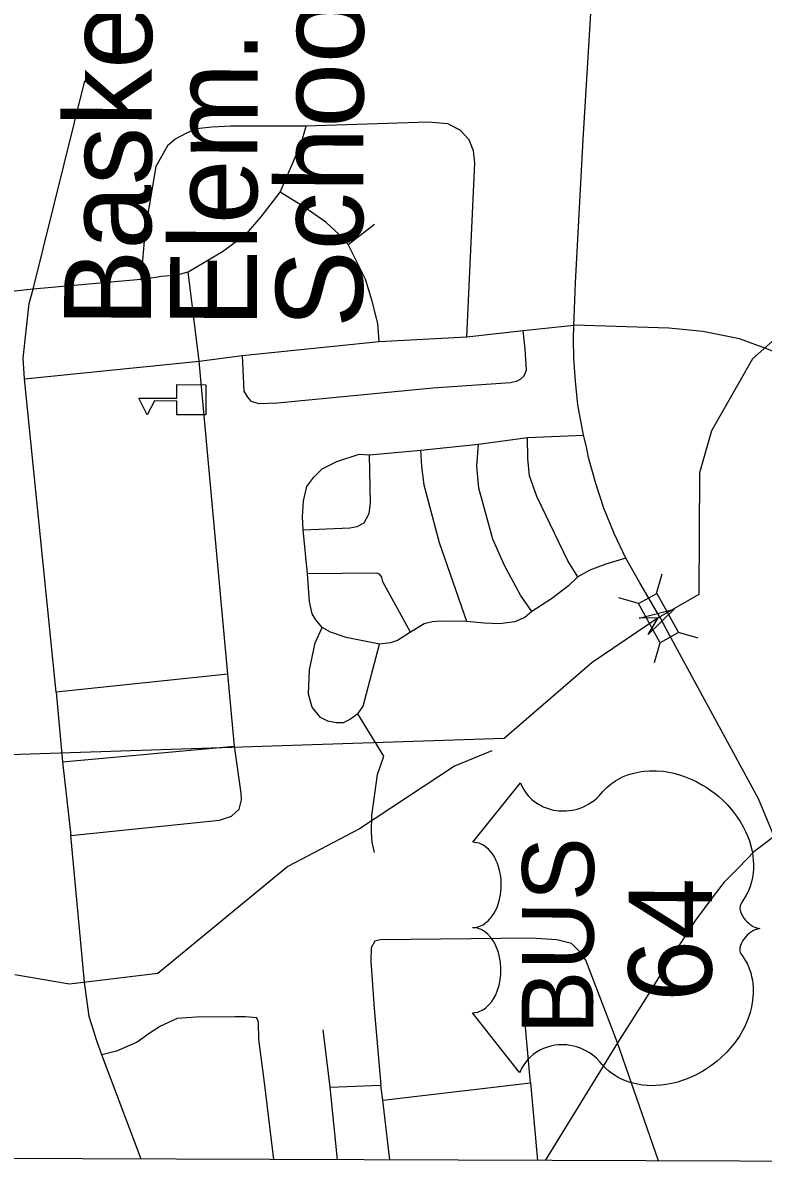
# Model space of a CAD drawing. Extents: x 2364794 to 2387902, y 795230 to 810426.
# Drawn here: x 2366376.7 to 2366649.7, y 800399.4 to 800821.1 of the extents above; entities that cross this region are included whole.
import ezdxf

# ---------------------------------------------------------------- set-up
doc = ezdxf.new("R2010")
doc.units = 0
for name, color, linetype in [('Default', 7, 'Continuous'), ('Plot Label CELL', 7, 'Continuous'), ('Plot Shape CELL', 7, 'Continuous')]:
    doc.layers.add(name, color=color, linetype=linetype)

msp = doc.modelspace()

# ---------------------------------------------------------------- linework, layer by layer
at = {"layer": 'Default'}
for p, q in [((2366610.39, 800610.6), (2366612.48, 800617.85)), ((2366603.79, 800606.95), (2366596.54, 800609.03)), ((2366625.77, 800594.12), (2366618.52, 800596.21)), ((2366609.68, 800585.22), (2366611.76, 800592.47)), ((2366599.77, 800543.72), (2366601.6, 800544.28)), ((2366601.6, 800544.28), (2366602.56, 800544.54)), ((2366602.56, 800544.54), (2366604.72, 800544.94)), ((2366604.72, 800544.94), (2366605.79, 800545.09)), ((2366605.79, 800545.09), (2366607.89, 800545.25)), ((2366607.89, 800545.25), (2366610.43, 800545.25)), ((2366610.43, 800545.25), (2366612.85, 800545.05)), ((2366612.85, 800545.05), (2366615.66, 800544.58)), ((2366615.66, 800544.58), (2366617.35, 800544.2)), ((2366617.35, 800544.2), (2366619.31, 800543.62)), ((2366542.68, 800518.86), (2366560.26, 800540.77)), ((2366560.26, 800540.77), (2366560.46, 800540.25)), ((2366560.46, 800540.25), (2366561.04, 800539.05)), ((2366592.05, 800539.03), (2366593.66, 800540.4)), ((2366593.66, 800540.4), (2366594.41, 800540.95)), ((2366594.41, 800540.95), (2366595.26, 800541.52)), ((2366595.26, 800541.52), (2366596.13, 800542.03)), ((2366596.13, 800542.03), (2366597.06, 800542.55)), ((2366597.06, 800542.55), (2366597.88, 800542.96)), ((2366597.88, 800542.96), (2366599.77, 800543.72)), ((2366619.31, 800543.62), (2366621.01, 800543.05)), ((2366621.01, 800543.05), (2366623.51, 800542.04)), ((2366623.51, 800542.04), (2366625.32, 800541.14)), ((2366625.32, 800541.14), (2366627.45, 800539.98)), ((2366627.45, 800539.98), (2366628.73, 800539.18)), ((2366561.04, 800539.05), (2366561.59, 800538.11)), ((2366561.59, 800538.11), (2366562.65, 800536.59)), ((2366562.65, 800536.59), (2366563.23, 800535.94)), ((2366563.23, 800535.94), (2366563.84, 800535.29)), ((2366588.47, 800535.2), (2366589.41, 800536.11)), ((2366589.41, 800536.11), (2366590.56, 800537.46)), ((2366590.56, 800537.46), (2366591.21, 800538.19)), ((2366591.21, 800538.19), (2366592.05, 800539.03)), ((2366628.73, 800539.18), (2366630.1, 800538.26)), ((2366630.1, 800538.26), (2366631.68, 800537.1)), ((2366631.68, 800537.1), (2366633.37, 800535.74)), ((2366633.37, 800535.74), (2366635.14, 800534.11)), ((2366563.84, 800535.29), (2366564.49, 800534.69)), ((2366564.49, 800534.69), (2366565.1, 800534.16)), ((2366565.1, 800534.16), (2366565.98, 800533.52)), ((2366565.98, 800533.52), (2366566.86, 800532.95)), ((2366566.86, 800532.95), (2366567.83, 800532.39)), ((2366567.83, 800532.39), (2366568.67, 800531.97)), ((2366568.67, 800531.97), (2366570.44, 800531.29)), ((2366570.44, 800531.29), (2366571.55, 800530.97)), ((2366581.11, 800531.14), (2366582.33, 800531.52)), ((2366582.33, 800531.52), (2366583.51, 800532)), ((2366583.51, 800532), (2366585.42, 800533)), ((2366585.42, 800533), (2366587.38, 800534.28)), ((2366587.38, 800534.28), (2366588.47, 800535.2)), ((2366635.14, 800534.11), (2366636.45, 800532.8)), ((2366636.45, 800532.8), (2366637.97, 800531.08)), ((2366571.55, 800530.97), (2366572.5, 800530.75)), ((2366572.5, 800530.75), (2366574.46, 800530.49)), ((2366574.46, 800530.49), (2366575.39, 800530.42)), ((2366575.39, 800530.42), (2366576.31, 800530.42)), ((2366576.31, 800530.42), (2366577.29, 800530.46)), ((2366577.29, 800530.46), (2366578.22, 800530.55)), ((2366578.22, 800530.55), (2366579.2, 800530.72)), ((2366579.2, 800530.72), (2366580.05, 800530.87)), ((2366580.05, 800530.87), (2366581.11, 800531.14)), ((2366637.97, 800531.08), (2366638.83, 800530.04)), ((2366638.83, 800530.04), (2366639.94, 800528.56)), ((2366639.94, 800528.56), (2366641.28, 800526.53)), ((2366641.28, 800526.53), (2366642.43, 800524.53)), ((2366642.43, 800524.53), (2366643.29, 800522.82)), ((2366643.29, 800522.82), (2366643.94, 800521.31)), ((2366543.33, 800518.84), (2366542.68, 800518.86)), ((2366544.1, 800518.73), (2366543.33, 800518.84)), ((2366544.98, 800518.51), (2366544.1, 800518.73)), ((2366643.94, 800521.31), (2366644.67, 800519.37)), ((2366644.67, 800519.37), (2366645.55, 800516.12)), ((2366545.81, 800518.16), (2366544.98, 800518.51)), ((2366546.6, 800517.78), (2366545.81, 800518.16)), ((2366547.37, 800517.24), (2366546.6, 800517.78)), ((2366548.42, 800516.33), (2366547.37, 800517.24)), ((2366549.29, 800515.37), (2366548.42, 800516.33)), ((2366549.94, 800514.56), (2366549.29, 800515.37)), ((2366550.63, 800513.46), (2366549.94, 800514.56)), ((2366645.55, 800516.12), (2366645.8, 800514.94)), ((2366645.8, 800514.94), (2366646, 800513.54)), ((2366551.33, 800512.09), (2366550.63, 800513.46)), ((2366551.79, 800511.04), (2366551.33, 800512.09)), ((2366552.21, 800509.84), (2366551.79, 800511.04)), ((2366646, 800513.54), (2366646.13, 800512.22)), ((2366646.13, 800512.22), (2366646.2, 800510.95)), ((2366646.2, 800510.95), (2366646.19, 800509.24)), ((2366552.56, 800508.52), (2366552.21, 800509.84)), ((2366552.77, 800507.52), (2366552.56, 800508.52)), ((2366552.98, 800506.27), (2366552.77, 800507.52)), ((2366553.1, 800505.14), (2366552.98, 800506.27)), ((2366646.06, 800507.54), (2366645.82, 800505.93)), ((2366646.19, 800509.24), (2366646.06, 800507.54)), ((2366553.05, 800500.68), (2366553.14, 800501.87)), ((2366553.16, 800504.04), (2366553.1, 800505.14)), ((2366553.14, 800501.87), (2366553.17, 800502.85)), ((2366553.17, 800502.85), (2366553.16, 800504.04)), ((2366644.94, 800502.51), (2366644.31, 800500.92)), ((2366645.46, 800504.26), (2366644.94, 800502.51)), ((2366645.82, 800505.93), (2366645.46, 800504.26)), ((2366552.4, 800497.22), (2366552.67, 800498.37)), ((2366552.67, 800498.37), (2366552.87, 800499.51)), ((2366552.87, 800499.51), (2366553.05, 800500.68)), ((2366643.51, 800499.31), (2366641.79, 800496.6)), ((2366644.31, 800500.92), (2366643.51, 800499.31)), ((2366550.47, 800492.62), (2366551.36, 800494.37)), ((2366551.36, 800494.37), (2366551.74, 800495.22)), ((2366551.74, 800495.22), (2366552.06, 800496.1)), ((2366552.06, 800496.1), (2366552.4, 800497.22)), ((2366641.25, 800495.38), (2366641.19, 800494.33)), ((2366641.19, 800494.33), (2366641.4, 800493.34)), ((2366641.37, 800495.82), (2366641.25, 800495.38)), ((2366641.79, 800496.6), (2366641.37, 800495.82)), ((2366641.4, 800493.34), (2366641.8, 800492.33)), ((2366547.25, 800488.99), (2366548.41, 800489.97)), ((2366548.41, 800489.97), (2366548.99, 800490.58)), ((2366548.99, 800490.58), (2366549.44, 800491.13)), ((2366549.44, 800491.13), (2366550.47, 800492.62)), ((2366641.8, 800492.33), (2366642.12, 800491.72)), ((2366642.12, 800491.72), (2366642.65, 800490.9)), ((2366642.65, 800490.9), (2366643.14, 800490.28)), ((2366643.14, 800490.28), (2366643.85, 800489.52)), ((2366643.85, 800489.52), (2366644.45, 800489)), ((2366542.59, 800487.42), (2366543.61, 800487.49)), ((2366543.81, 800487.32), (2366542.59, 800487.42)), ((2366543.61, 800487.49), (2366544.25, 800487.59)), ((2366544.39, 800487.19), (2366543.81, 800487.32)), ((2366544.25, 800487.59), (2366544.87, 800487.76)), ((2366545.71, 800486.72), (2366544.39, 800487.19)), ((2366544.87, 800487.76), (2366545.54, 800488.01)), ((2366545.54, 800488.01), (2366546.47, 800488.48)), ((2366546.34, 800486.38), (2366545.71, 800486.72)), ((2366546.98, 800485.99), (2366546.34, 800486.38)), ((2366546.47, 800488.48), (2366547.25, 800488.99)), ((2366548.14, 800485.06), (2366546.98, 800485.99)), ((2366549.25, 800483.89), (2366548.14, 800485.06)), ((2366644.76, 800485.33), (2366643.87, 800484.57)), ((2366644.45, 800489), (2366644.91, 800488.6)), ((2366645.45, 800485.81), (2366644.76, 800485.33)), ((2366644.91, 800488.6), (2366646.12, 800487.83)), ((2366646.23, 800486.28), (2366645.45, 800485.81)), ((2366646.12, 800487.83), (2366646.69, 800487.56)), ((2366647.14, 800486.68), (2366646.23, 800486.28)), ((2366646.69, 800487.56), (2366647.43, 800487.27)), ((2366648.51, 800487.02), (2366647.14, 800486.68)), ((2366647.43, 800487.27), (2366648.51, 800487.02)), ((2366549.84, 800483.06), (2366549.25, 800483.89)), ((2366550.51, 800482.01), (2366549.84, 800483.06)), ((2366551.21, 800480.69), (2366550.51, 800482.01)), ((2366551.7, 800479.5), (2366551.21, 800480.69)), ((2366641.38, 800480.82), (2366641.18, 800480.03)), ((2366641.63, 800481.47), (2366641.38, 800480.82)), ((2366641.99, 800482.17), (2366641.63, 800481.47)), ((2366642.53, 800483.05), (2366641.99, 800482.17)), ((2366643.21, 800483.88), (2366642.53, 800483.05)), ((2366643.87, 800484.57), (2366643.21, 800483.88)), ((2366552.14, 800478.21), (2366551.7, 800479.5)), ((2366552.43, 800477.06), (2366552.14, 800478.21)), ((2366552.9, 800474.56), (2366552.43, 800477.06)), ((2366641.18, 800480.03), (2366641.13, 800479.38)), ((2366641.13, 800479.38), (2366641.14, 800478.85)), ((2366641.14, 800478.85), (2366641.3, 800478.11)), ((2366641.3, 800478.11), (2366642.02, 800477.12)), ((2366642.02, 800477.12), (2366642.66, 800476.17)), ((2366553.06, 800472.31), (2366552.9, 800474.56)), ((2366553.02, 800470.22), (2366553.06, 800472.31)), ((2366642.66, 800476.17), (2366643.29, 800475.15)), ((2366643.29, 800475.15), (2366643.94, 800473.92)), ((2366643.94, 800473.92), (2366644.35, 800473.03)), ((2366644.35, 800473.03), (2366644.76, 800471.96)), ((2366552.38, 800466.17), (2366552.78, 800468.1)), ((2366552.78, 800468.1), (2366553.02, 800470.22)), ((2366644.76, 800471.96), (2366645.17, 800470.72)), ((2366645.17, 800470.72), (2366645.52, 800469.36)), ((2366645.52, 800469.36), (2366645.79, 800467.98)), ((2366551.11, 800462.58), (2366551.83, 800464.28)), ((2366551.83, 800464.28), (2366552.38, 800466.17)), ((2366645.79, 800467.98), (2366645.98, 800466.75)), ((2366645.98, 800466.75), (2366646.09, 800465.44)), ((2366646.09, 800465.44), (2366646.12, 800464.26)), ((2366646.12, 800464.26), (2366646.11, 800463.03)), ((2366548.64, 800458.9), (2366549.72, 800460.2)), ((2366549.72, 800460.2), (2366550.3, 800461.08)), ((2366550.3, 800461.08), (2366551.11, 800462.58)), ((2366645.89, 800460.54), (2366645.64, 800458.88)), ((2366646.01, 800461.88), (2366645.89, 800460.54)), ((2366646.11, 800463.03), (2366646.01, 800461.88)), ((2366542.53, 800455.97), (2366543.44, 800456.03)), ((2366559.95, 800433.94), (2366542.53, 800455.97)), ((2366543.44, 800456.03), (2366544.52, 800456.24)), ((2366544.52, 800456.24), (2366545.07, 800456.41)), ((2366545.07, 800456.41), (2366546.14, 800456.91)), ((2366546.14, 800456.91), (2366547.4, 800457.74)), ((2366547.4, 800457.74), (2366548.64, 800458.9)), ((2366644.93, 800456.05), (2366644.45, 800454.56)), ((2366645.32, 800457.51), (2366644.93, 800456.05)), ((2366645.64, 800458.88), (2366645.32, 800457.51)), ((2366643.84, 800452.97), (2366642.96, 800450.97)), ((2366644.45, 800454.56), (2366643.84, 800452.97)), ((2366640.98, 800447.4), (2366639.19, 800444.84)), ((2366642.24, 800449.59), (2366640.98, 800447.4)), ((2366642.96, 800450.97), (2366642.24, 800449.59)), ((2366568.73, 800442.82), (2366567.67, 800442.33)), ((2366570.19, 800443.36), (2366568.73, 800442.82)), ((2366571.46, 800443.7), (2366570.19, 800443.36)), ((2366572.92, 800443.98), (2366571.46, 800443.7)), ((2366574.44, 800444.14), (2366572.92, 800443.98)), ((2366575.74, 800444.18), (2366574.44, 800444.14)), ((2366577.31, 800444.11), (2366575.74, 800444.18)), ((2366578.57, 800443.94), (2366577.31, 800444.11)), ((2366579.9, 800443.67), (2366578.57, 800443.94)), ((2366580.94, 800443.41), (2366579.9, 800443.67)), ((2366582.42, 800442.9), (2366580.94, 800443.41)), ((2366583.38, 800442.5), (2366582.42, 800442.9)), ((2366637.61, 800442.9), (2366636.32, 800441.49)), ((2366639.19, 800444.84), (2366637.61, 800442.9)), ((2366562.81, 800438.62), (2366562.08, 800437.69)), ((2366563.79, 800439.59), (2366562.81, 800438.62)), ((2366564.88, 800440.56), (2366563.79, 800439.59)), ((2366566.22, 800441.49), (2366564.88, 800440.56)), ((2366567.67, 800442.33), (2366566.22, 800441.49)), ((2366584.66, 800441.82), (2366583.38, 800442.5)), ((2366585.53, 800441.32), (2366584.66, 800441.82)), ((2366586.5, 800440.68), (2366585.53, 800441.32)), ((2366587.55, 800439.87), (2366586.5, 800440.68)), ((2366588.3, 800439.21), (2366587.55, 800439.87)), ((2366589.54, 800437.93), (2366588.3, 800439.21)), ((2366634.18, 800439.4), (2366632.79, 800438.18)), ((2366636.32, 800441.49), (2366634.18, 800439.4)), ((2366560.23, 800434.62), (2366559.95, 800433.94)), ((2366560.76, 800435.69), (2366560.23, 800434.62)), ((2366561.44, 800436.81), (2366560.76, 800435.69)), ((2366562.08, 800437.69), (2366561.44, 800436.81)), ((2366590.41, 800436.86), (2366589.54, 800437.93)), ((2366591.52, 800435.69), (2366590.41, 800436.86)), ((2366592.74, 800434.56), (2366591.52, 800435.69)), ((2366593.84, 800433.7), (2366592.74, 800434.56)), ((2366628.48, 800435.04), (2366627.15, 800434.24)), ((2366630.29, 800436.26), (2366628.48, 800435.04)), ((2366632.79, 800438.18), (2366630.29, 800436.26)), ((2366595.13, 800432.83), (2366593.84, 800433.7)), ((2366596.34, 800432.13), (2366595.13, 800432.83)), ((2366597.79, 800431.4), (2366596.34, 800432.13)), ((2366599.31, 800430.77), (2366597.79, 800431.4)), ((2366600.68, 800430.3), (2366599.31, 800430.77)), ((2366601.81, 800429.98), (2366600.68, 800430.3)), ((2366617.18, 800430.15), (2366615.3, 800429.74)), ((2366618.26, 800430.44), (2366617.18, 800430.15)), ((2366619.95, 800430.97), (2366618.26, 800430.44)), ((2366621.73, 800431.62), (2366619.95, 800430.97)), ((2366623.68, 800432.45), (2366621.73, 800431.62)), ((2366625.02, 800433.08), (2366623.68, 800432.45)), ((2366627.15, 800434.24), (2366625.02, 800433.08)), ((2366603.38, 800429.63), (2366601.81, 800429.98)), ((2366605.21, 800429.33), (2366603.38, 800429.63)), ((2366606.93, 800429.15), (2366605.21, 800429.33)), ((2366608.41, 800429.1), (2366606.93, 800429.15)), ((2366610.19, 800429.12), (2366608.41, 800429.1)), ((2366612.13, 800429.25), (2366610.19, 800429.12)), ((2366613.96, 800429.49), (2366612.13, 800429.25)), ((2366615.3, 800429.74), (2366613.96, 800429.49))]:
    msp.add_line(p, q, dxfattribs=at)
for points in [[(2365221.07, 800406.27), (2365228.68, 802558.07), (2367168.28, 802551.22), (2367160.68, 800399.42)], [(2365221.07, 800406.27), (2365228.68, 802558.07), (2367168.28, 802551.22), (2367160.68, 800399.42)], [(2366444.21, 800676.55), (2366433.5, 800676.59), (2366433.52, 800681.63), (2366425.31, 800681.66), (2366422.64, 800676.52), (2366419.47, 800682.73), (2366433.53, 800682.68), (2366433.54, 800687.71), (2366444.25, 800687.67)], [(2366611.76, 800592.47), (2366603.76, 800606.93), (2366610.52, 800610.67), (2366618.52, 800596.21)], [(2366603.98, 800601.58), (2366616.9, 800604.87), (2366607.36, 800595.56), (2366611.08, 800601.61)]]:
    msp.add_lwpolyline(points, close=True, dxfattribs=at)
at = {"layer": 'Plot Label CELL'}
for p, q in [((2366380.52, 800722.89), (2366399.54, 800799.77)), ((2366496.67, 800739.39), (2366506.45, 800746.9)), ((2366420.26, 800726.49), (2366380.52, 800722.89)), ((2366441.73, 800696.3), (2366437.74, 800729.27)), ((2366561.2, 800707.66), (2366579.9, 800709.63)), ((2366508.14, 800703.63), (2366540.47, 800705.3)), ((2366540.47, 800705.3), (2366561.2, 800707.66)), ((2366457.66, 800698.4), (2366508.14, 800703.63)), ((2366377.3, 800689.85), (2366441.73, 800696.3)), ((2366441.73, 800696.3), (2366457.66, 800698.4)), ((2366452.33, 800580.94), (2366441.73, 800696.3)), ((2366389.02, 800574.28), (2366377.3, 800689.85)), ((2366544.74, 800665.68), (2366562.87, 800668.24)), ((2366562.87, 800668.24), (2366583.52, 800669.1)), ((2366504.56, 800661.84), (2366523.57, 800663.53)), ((2366523.57, 800663.53), (2366544.74, 800665.68)), ((2366481.75, 800617.94), (2366480.08, 800634.09)), ((2366452.33, 800580.94), (2366389.02, 800574.28)), ((2366454.75, 800554.31), (2366452.33, 800580.94)), ((2366389.02, 800574.28), (2366391.39, 800548.53)), ((2366391.39, 800548.53), (2366454.75, 800554.31)), ((2366391.39, 800548.53), (2366394.38, 800521.33)), ((2366564.01, 800430.18), (2366561.85, 800453.34)), ((2366490.02, 800428.53), (2366487.45, 800449.66)), ((2366611.19, 800401.36), (2366596.04, 800444.87)), ((2366509.51, 800423.79), (2366564.01, 800430.18)), ((2366564.01, 800430.18), (2366566.56, 800401.52)), ((2366490.02, 800428.53), (2366508.72, 800429.28)), ((2366492.83, 800401.78), (2366490.02, 800428.53)), ((2366509.51, 800423.79), (2366508.72, 800429.28)), ((2366512.04, 800401.71), (2366509.51, 800423.79))]:
    msp.add_line(p, q, dxfattribs=at)
for points in [[(2366788.16, 801000.92), (2366786.07, 800825.96), (2366768.32, 800782.08), (2366754.11, 800740.13), (2366744.07, 800730.01), (2366706.87, 800726.96), (2366678.73, 800721.27), (2366665.69, 800714.75), (2366645.89, 800697.21), (2366630.73, 800670.7), (2366626.28, 800655.17), (2366626.04, 800610.32), (2366611.08, 800601.61), (2366586.72, 800585.24), (2366554.22, 800557.13), (2366241.62, 800546.88), (2366175.9, 800494.71), (2366184.14, 800414.1)], [(2366540.47, 800705.3), (2366543.42, 800769.52), (2366542.95, 800773.88), (2366541.39, 800778.03), (2366538.07, 800781.5), (2366533.47, 800783.87), (2366526.26, 800784.46), (2366481.22, 800782.97)], [(2366481.22, 800782.97), (2366453.46, 800782.97), (2366446.47, 800782.69), (2366440.79, 800781.99), (2366437.09, 800780.44), (2366432.95, 800778.2), (2366430.13, 800775.77), (2366425.82, 800768.09), (2366421.87, 800744.89), (2366420.26, 800726.49)], [(2366471.59, 800758.65), (2366479.32, 800776.63), (2366481.22, 800782.97)], [(2366437.74, 800729.27), (2366450.35, 800736.81), (2366459.04, 800743.23), (2366464.68, 800749.62), (2366471.59, 800758.65)], [(2366496.67, 800739.39), (2366493.36, 800743.09), (2366488.51, 800747.64), (2366480.38, 800753.23), (2366471.59, 800758.65)], [(2366508.14, 800703.63), (2366507.62, 800710.2), (2366505.59, 800718.48), (2366503.12, 800726.55), (2366496.67, 800739.39)], [(2366420.26, 800726.49), (2366427.91, 800727.66), (2366433.59, 800728.15), (2366437.74, 800729.27)], [(2366380.52, 800722.89), (2366364.57, 800721.22), (2366338.64, 800716.12)], [(2366377.3, 800689.85), (2366376.81, 800697.48), (2366379.02, 800717.63), (2366380.52, 800722.89)], [(2366664.27, 800695.42), (2366660.13, 800697.05), (2366651.79, 800700.7), (2366641.04, 800704.54), (2366627.46, 800707.27), (2366614.99, 800708.48), (2366579.9, 800709.63)], [(2366457.66, 800698.4), (2366458.22, 800685.3), (2366459.55, 800683.12), (2366460.87, 800681.59), (2366463.72, 800680.73), (2366470.71, 800681.01), (2366527.96, 800686.54), (2366556.57, 800688.52), (2366558.76, 800688.98), (2366560.28, 800689.65), (2366561.58, 800690.97), (2366562.42, 800693.16), (2366561.99, 800700.75), (2366561.2, 800707.66)], [(2366581.44, 800616.8), (2366577.68, 800622.68), (2366566.34, 800646.4), (2366563.64, 800654.04), (2366562.93, 800660.39), (2366562.87, 800668.24)], [(2366480.08, 800634.09), (2366479.82, 800638.91), (2366480.21, 800644.81), (2366481.47, 800650.07), (2366484.08, 800653.6), (2366487.12, 800656.66), (2366492.55, 800659.34), (2366500.83, 800662.03), (2366504.56, 800661.84)], [(2366540.49, 800600.29), (2366530.4, 800629.27), (2366524.77, 800650.65), (2366523.83, 800657.64), (2366523.57, 800663.53)], [(2366564.5, 800603.98), (2366560.29, 800610.06), (2366554.32, 800620.95), (2366550.08, 800630.74), (2366544.87, 800649.52), (2366544.16, 800657.59), (2366544.74, 800665.68)], [(2366480.08, 800634.09), (2366497.35, 800634.91), (2366499.97, 800635.35), (2366502.59, 800636.7), (2366504.51, 800640.2), (2366504.92, 800643.92), (2366504.56, 800661.84)], [(2366599.07, 800623.7), (2366591.69, 800621.49), (2366585.79, 800619.26), (2366581.44, 800616.8)], [(2366519.75, 800596.38), (2366509.54, 800614.89), (2366509.09, 800616.64), (2366508.22, 800617.73), (2366507.32, 800618.15), (2366481.75, 800617.94)], [(2366487.15, 800598.09), (2366484.73, 800600.9), (2366483.41, 800603.08), (2366482.48, 800607.66), (2366481.75, 800617.94)], [(2366581.44, 800616.8), (2366577.98, 800613.5), (2366571.68, 800608.65), (2366564.5, 800603.98)], [(2366564.5, 800603.98), (2366561.89, 800601.79), (2366558.19, 800600.23), (2366552.51, 800599.51), (2366546.84, 800599.69), (2366540.49, 800600.29)], [(2366540.49, 800600.29), (2366530.87, 800600.44), (2366527.81, 800600.18), (2366524.75, 800599.51), (2366519.75, 800596.38)], [(2366500.32, 800566.28), (2366497.52, 800564.29), (2366494.9, 800562.96), (2366492.28, 800562.92), (2366489.21, 800563.55), (2366486.57, 800564.86), (2366483.48, 800568.76), (2366482.12, 800573.54), (2366482.48, 800582.53), (2366484.59, 800592.39), (2366487.15, 800598.09)], [(2366508.21, 800591.93), (2366495.93, 800594.45), (2366490.24, 800596.36), (2366487.15, 800598.09)], [(2366519.75, 800596.38), (2366514.96, 800593.3), (2366512.35, 800592.39), (2366508.21, 800591.93)], [(2366500.32, 800566.28), (2366502.28, 800569.13), (2366508.21, 800591.93)], [(2366506.45, 800515.16), (2366505.55, 800518.87), (2366505.31, 800522.6), (2366505.47, 800528.71), (2366507.51, 800543.82), (2366509.86, 800550.62), (2366500.32, 800566.28)], [(2366549.73, 800552.55), (2366535.94, 800546.92), (2366500.91, 800523.86), (2366474.51, 800509.96), (2366426.47, 800470.42), (2366393.96, 800466.5), (2366373.73, 800469.96)], [(2366394.38, 800521.33), (2366449.26, 800527.09), (2366453.67, 800528.5), (2366456.46, 800531.15), (2366457.41, 800534.51), (2366457.29, 800537.05), (2366454.75, 800554.31)], [(2366405.86, 800440.43), (2366404, 800445.62), (2366401.15, 800454.6), (2366399.51, 800467.25), (2366394.38, 800521.33)], [(2366653.77, 800520.95), (2366649.72, 800517.93), (2366646.26, 800515.41), (2366640.8, 800509.62), (2366635.33, 800504.2), (2366631.14, 800498.77), (2366624.76, 800490.09), (2366615.09, 800475.24), (2366606.32, 800461.12), (2366596.04, 800444.87), (2366569.33, 800401.51)], [(2366596.04, 800444.87), (2366584.4, 800475.39), (2366582.18, 800478.44), (2366579.1, 800481.48), (2366573.61, 800482.95), (2366564.21, 800483.52), (2366508.47, 800482.84), (2366506.52, 800482.38), (2366505.14, 800479.95), (2366505.12, 800475.08), (2366506.28, 800457.61), (2366508.72, 800429.28)], [(2366469.27, 800401.86), (2366465.85, 800430.24), (2366463.74, 800446.09), (2366463.63, 800452.45), (2366463.09, 800454.08), (2366458.89, 800454.5), (2366454.96, 800454.51), (2366440.74, 800454.43), (2366433.7, 800453.91), (2366427.46, 800451.09), (2366423.65, 800448.53), (2366418.94, 800445.12), (2366411.32, 800441.8), (2366405.86, 800440.43)], [(2366420.31, 800402.04), (2366405.86, 800440.43)]]:
    msp.add_lwpolyline(points, dxfattribs=at)
at = {"layer": 'Plot Shape CELL'}
for points in [[(2366579.89, 800709.28), (2366580.53, 800725.23), (2366583.37, 800778.16), (2366586.25, 800824.76), (2366586.76, 800840.29), (2366587.07, 800856.03), (2366587.58, 800871.56), (2366588.34, 800884.74)], [(2366653.77, 800520.95), (2366648.04, 800534.92), (2366615.14, 800595.55), (2366611.86, 800601.58), (2366604.32, 800614.61), (2366599.07, 800623.7), (2366594.77, 800632.78), (2366591.01, 800642.13), (2366588.06, 800651.22), (2366585.39, 800660.84), (2366584.59, 800664.77), (2366583.52, 800669.1), (2366581.46, 800680.28), (2366580.54, 800688.94), (2366579.89, 800697.34), (2366579.78, 800704.65), (2366579.89, 800709.28)]]:
    msp.add_lwpolyline(points, dxfattribs=at)

# ---------------------------------------------------------------- texts
at = {"layer": 'Default'}
for s, height, p in [('Baskerville', 32.0361, (2366423.97, 800708.88)), ('School', 32.036, (2366502.06, 800708.6)), ('Elem.', 32.036, (2366463.02, 800708.74)), ('BUS', 26.483, (2366587.15, 800447.9)), ('64', 30.755, (2366630.74, 800459.96))]:
    msp.add_text(s, height=height, rotation=89.7976, dxfattribs=at).set_placement(p)

doc.saveas('drawing.dxf')
